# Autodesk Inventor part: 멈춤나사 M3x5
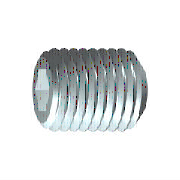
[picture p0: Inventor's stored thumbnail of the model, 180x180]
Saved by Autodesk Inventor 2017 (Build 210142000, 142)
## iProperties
Created: 2012-02
Part Number: 멈춤나사 M3x5
Material: 강철, 연강
Description: 6각 소켓 머리 없는 멈춤 나사
Document SubType Name: Modeling
Standard: KS B 1028
Designer: mduedu
Standards Organization: KS
Language: ko-KR
Size Designation: 납작점M3x5
Categories: <MemberInstance><Categories><Category DisplayName="조임쇠" InternalName="e4da775c-781d-43d5-af7c-5136215cf5a6" Mnemonic="FSTN"><Category DisplayName="볼트" InternalN
Density: 7.85 g/cm^3
Appearance: 노란색
Mass: 0.237365 g
Surface Area: 0.685518 cm^2
Volume: 0.0302376 cm^3
IsCustomPart: 1
Author: mduedu
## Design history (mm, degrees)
sketch "스케치1"
  geometry: L1 (0, 0)-(2.5, 0); L2 (5, 0.866)-(5, 1.5); L3 (5, 1.5)-(0, 1.5); L4 (5, 0.866)-(3, 0.866); L5 (3, 0.866)-(2.5, 0); L6 (0, -0.3)-(0, 1.8) reference; L7 (0, 1.5)-(0, 0)
  constraints: 13 end point, 3 parallel, 1 collinear, 1 perpendicular, 1 point on line
  dimensions: "d0" = 2 distance of L2.start L4.end (= INTI); "d1" = 60 deg angle of L5 L1; "d2" = 3 diameter of L3 L1 (= NND); "d3" = 1.73205 diameter of L4 L1 (= 1.1547 x SW); "d5" = 5 distance from line of L2 L3.end (= NLG)
revolve "본체" sketch "스케치1" stored, may be unused: angle "d6" = 90 deg
sketch "스케치2"
  geometry: L1 (-0.433, 0.75)-(0.433, 0.75); L2 (0.433, 0.75)-(0.866, 0); L3 (0.866, 0)-(0.433, -0.75); L4 (0.433, -0.75)-(-0.433, -0.75); L5 (-0.433, -0.75)-(-0.866, 0); L6 (-0.866, 0)-(-0.433, 0.75); A1 r 0.866 centre (0, 0) between (-0.433, 0.75) and (0.433, 0.75) reference; 2 further points
  constraints: 12 end point, 2 point on circle, 1 coincident, 1 horizontal, 11 other
extrude "슬롯" join sketch "스케치2" taper "d9" = 0 deg; stored distance "d21" = 10
workaxis "Work Axis1"
workplane "Work Plane1"
body "Solid1"
chamfer "모따기1" distance "d7" = 0.30673 (= -0.5 x GD1 + 0.5 x NND); stored, may be unused: angle "d8" = 45 deg (= FAWI), second distance "d29" = 0.30673 (= -0.5 x GD1 + 0.5 x NND)
feature "스레드" dims "d11" = 5 (= NLG), "d12" = 0
chamfer "모따기2" distance "d13" = 0.30673 (= -0.5 x GD1 + 0.5 x NND); stored, may be unused: angle "d14" = 45 deg (= FAWI), second distance "d30" = 0.30673 (= -0.5 x GD1 + 0.5 x NND)
other parameters: "NND" = 3 [user parameter; used in 5 equation terms], "NLG" = 5 [user parameter; used in 2 equation terms], "INTI" = 2 [user parameter; used in 1 equation term], "FAWI" = 45 deg [user parameter; used in 2 equation terms], "SW" = 1.5 [user parameter; used in 2 equation terms], "GD1" = 2.38655 (= THREADDIA - 1.2269 x PTC) [user parameter; used in 4 equation terms], "d4" = 0, "FAWI1" = 45 deg [user parameter], "d15" = 0, "d31" = 0, "GUL" = 0.30673 (= 0.61345 x PTC) [user parameter], "SPD" = 2 [user parameter], "TOA" = 30 deg [user parameter], "THREADDIA" = 3 [user parameter; used in 1 equation term], "PTC" = 0.5 [user parameter; used in 4 equation terms], "GAL" = 0.30673 (= 0.61345 x PTC) [user parameter], "E0" = 1.7325 (= 1.155 x SW) [user parameter]
